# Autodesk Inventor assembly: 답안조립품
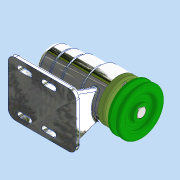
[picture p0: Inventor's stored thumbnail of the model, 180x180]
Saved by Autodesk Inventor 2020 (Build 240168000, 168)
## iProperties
Created: 2021-10
Part Number: 답안조립품
Document SubType Name: Assembly
Designer: user
Author: user
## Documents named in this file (12)
- C:\Users\user\Desktop\711007V1007\답안조립품.iam
- C:\Users\user\Desktop\711007V1007\본체.ipt
- C:\Users\user\Desktop\711007V1007\볼트 M4.ipt
- C:\Users\user\Desktop\711007V1007\어댑터슬리브.ipt
- C:\Users\user\Desktop\711007V1007\오일 실 20x35x7.ipt
- C:\Users\user\Desktop\711007V1007\축.ipt
- C:\Users\user\Desktop\711007V1007\커버.ipt
- C:\Users\user\Desktop\711007V1007\키 5x5.ipt
- C:\Users\user\Desktop\711007V1007\멈춤나사 M3.ipt
- C:\Users\user\Desktop\711007V1007\베어링 6004.ipt
- C:\Users\user\Desktop\711007V1007\베어링 51202.ipt
- C:\Users\user\Desktop\711007V1007\V벨트풀리.ipt
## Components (1 placed, 1 different names)
1. V벨트풀리:1
